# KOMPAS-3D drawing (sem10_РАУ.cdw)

Views: Разрез А-А, Вид Ж, Вид 1, Вид Е, Вид 2
Referenced files: AZZKOE CHERTILO 1.cdw
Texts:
  Автопилот стабилизации угла крена
  Рулевой агрегат управления
  Напряжение питания электродвигателя, В . . . . . . . . 27 2,7 В
  Скорость движения выходного штока, мм/сек  . . . . 50
  Рабочее усилие на выходном штоке, Н . . . . . . . . . . . 60
  Максимальный ход штока, мм . . . . . . . . . . . . . . . . 24
  Максимальное усилие на разрыв, Н . . . . . . . . . . . . . . 11000
  Диаметр и шаг передачи винт-гайка, мм . . . . . . . . . 12/3
  Текст
  Подшипник 4А-1000004 ГОСТ 10058-90
  Подшипник 36203 ГОСТ 831-75
  Выходной шток
  Подшипник 5А-1000004 ГОСТ 10058-90
  Шпонка 1x1,4 ГОСТ 24071-97
  Шайба 3 БрКМц3-1 ГОСТ 6402-70
  Шайба 4 БрКМц3-1 ГОСТ 6402-70
  Гайка М4-6H.04 ГОСТ 10657-80
  Винт А.М2-6gx4.109.30ХГСА ГОСТ 17475-80
  Шайба 5 БрКМц3-1 ГОСТ 6402-70
  Винт А.М5-6gx14.109.30ХГСА ГОСТ 1491-80
  Стопор винтовой
  Штифтовать так, чтобы винт делал
  от упора до упора 16 оборотов.
  Втулка подшипников
  Основной
  разрез Б-Б
  Винт А.М3-6gx8.109.30ХГСА ГОСТ 1491-80
  разрез В-В
  Шайба 2 БрКМц3-1 ГОСТ 6402-70
  разрез Д-Д
  Подшипник 4А-14 ГОСТ 10058-90
  Подшипник 5А-14 ГОСТ 10058-90
  Шайба A.4.31 ГОСТ 11371-78
  разрез Г-Г
  Схема
  Основная 0.4
  Двигатель ДПР-62-Ф1-03
  Стакан двигателя
  Подшипник 971067 ГОСТ 9592-75
  Подшипник
  ГОСТ
  Вилка
  Шайба пружинная
  Шайба
  БрКМц3-1
  БрКМц3-1 ГОСТ 18175-78
  Винт В.М 2-6g x 3.109.30ХГСА ГОСТ 1491-80
  Винт обычный
  Винт
  .30ХГСА
  Сталь 30ХГСА ГОСТ 4543-71
  Винт А.М 5-6g x 16.109.30ХГСА ГОСТ 1491-80
  Винт А.М 5-6g x 14.109.30ХГСА ГОСТ 1491-80
  Винт А.М 3-6g x 8.109.30ХГСА ГОСТ 1491-80
  Лит-Масса-Масштаб
  Материал-Предприятие
  Title Specification
  Body Specification ( left align )
  Body Specificaton ( centered )
  Поз.
  Кол.
  Приме-
  чание
  Таблица спецификации
  Стили документа
  Рулевой агрегат
  управления
  Пашинин С.А.
  Окоемов Б.Н.
  МГТУ им. Н.Э. Баумана
  Кафедра ИУ2
  Группа ИУ2-102
Dimensions and other numbers on the sheet: 14; 383; 1; 12; 4; 16; 10; 7H/7f; 17; 2 подшипника; 6; 7; 4 подшипника; 18; 8; 24; 22; 23; 29; 13; 20; 27; 11; 15; 39; 31; 9; 19; 2; 26; 32; 30; 28; 5; 3; 140; 40; 46; 52; 208; 57; 2,5; 1,5; 34; 33,6; 10,4; 82; 88; 33; 35; 108; 96; 47; 55; 36; 029; 70; -6g; 80; 2:1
